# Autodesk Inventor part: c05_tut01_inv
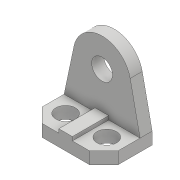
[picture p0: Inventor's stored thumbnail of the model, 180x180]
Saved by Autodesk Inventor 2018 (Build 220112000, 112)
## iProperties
Created: 2017-04
Part Number: c05_tut01_inv
Material: Generic
Document SubType Name: Modeling
Designer: CADCIM 00
Density: 1 g/cm^3
Appearance: Default
Author: CADCIM 00
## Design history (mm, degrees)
sketch "Sketch1"
  geometry: L1 (0, 0)-(-201.046, 0); L2 (-201.046, 0)-(-201.046, -90); L3 (-201.046, -90)-(-163.046, -128); L4 (-163.046, -128)-(-38, -128); L5 (-38, -128)-(0, -90); L6 (0, -90)-(0, 0); L7 (-201.046, -90)-(0, -90); C1 r 26 at (-155.046, -74); C2 r 26 at (-46, -74)
  constraints: 14 end point, 3 horizontal, 3 perpendicular, 2 centre point, 1 equal radius, 1 horizontal alignment
  dimensions: "d0" = 90 distance of L1.end L2.end; "d1" = 128 distance between parallel lines of L1 L4; "d2" = 38 distance from line of L3.end L2; "d3" = 125.04604 distance of L3.end L4.end; "d4" = 46 distance from line of L2 C1.centre; "d5" = 74 distance from line of L1 C1.centre; "d6" = 52 diameter of C1; "d7" = 46 distance from line of L6 C2.centre
extrude "Extrusion1" new body sketch "Sketch1" distance "d8" = 32; taper "d9" = 0 deg
sketch "Sketch2"
  geometry: L1 (201.046, -32)-(0, -32) reference; L2 (201.046, -32)-(174.878, -155.726); L3 (26.168, -155.726)-(0, -32); L4 (0, -32)-(201.046, -32); L5 (100.523, -32)-(100.523, -140); C1 r 27.5 at (100.523, -140); A1 r 76 centre (100.523, -140) between (26.168, -155.726) and (174.878, -155.726); 1 further point
  constraints: 8 end point, 2 centre point, 2 point on circle, 2 tangent, 1 coincident, 1 collinear, 1 midpoint, 1 vertical
  dimensions: "d10" = 55 diameter of C1; "d11" = 76 radius of A1; "d12" = 108 distance from line of L1 A1.centre
extrude "Extrusion2" join sketch "Sketch2" distance "d13" = 32; taper "d14" = 0 deg
sketch "Sketch3"
  geometry: L1 (82, 42)-(118, 42); L2 (118, 42)-(118, 32); L3 (118, 32)-(82, 32); L4 (82, 32)-(82, 42); L5 (38, 32)-(163.046, 32) reference; L6 (0, 0)-(0, 32) reference; 1 further point
  constraints: 8 end point, 2 parallel, 1 collinear, 1 horizontal, 1 perpendicular
  dimensions: "d15" = 10 distance between parallel lines of L3 L1; "d16" = 36 distance of L1.start L1.end; "d17" = 82 distance from line of L6 L1.start
extrude "Extrusion3" join sketch "Sketch3" stored distance "d18" = 32; taper "d19" = 0 deg
body "Solid1"
